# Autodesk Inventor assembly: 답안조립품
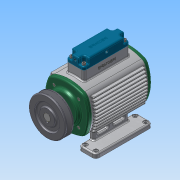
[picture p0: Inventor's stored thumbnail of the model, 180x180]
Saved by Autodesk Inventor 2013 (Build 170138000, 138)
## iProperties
Created: 2015-11
Part Number: 답안조립품
Document SubType Name: Assembly
Designer: Administrator
Mass: 3987.76 g
Surface Area: 3185.16 cm^2
Volume: 1076.11 cm^3
Density: 3.70574 g/cm^3
Author: Administrator
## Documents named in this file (18)
- C:\Users\Administrator\Desktop\351110V1036\답안조립품.iam
- C:\Users\Administrator\Desktop\351110V1036\본체.ipt
- C:\Users\Administrator\Desktop\351110V1036\축.ipt
- C:\Users\Administrator\Desktop\351110V1036\V-벨트풀리.ipt
- C:\Users\Administrator\Desktop\351110V1036\베어링 6203.ipt
- C:\Users\Administrator\Desktop\351110V1036\볼트 M4 x 12.ipt
- C:\Users\Administrator\Desktop\351110V1036\앞커버.ipt
- C:\Users\Administrator\Desktop\351110V1036\오일실 17 30 8.ipt
- C:\Users\Administrator\Desktop\351110V1036\키 - 5 x 5 x 18.ipt
- C:\Users\Administrator\Desktop\351110V1036\멈춤나사 M4x5.ipt
- C:\Users\Administrator\Desktop\351110V1036\뒷커버.ipt
- C:\Users\Administrator\Desktop\351110V1036\부시.ipt
- C:\Users\Administrator\Desktop\351110V1036\스프링1.ipt
- C:\Users\Administrator\Desktop\351110V1036\슬라이드.ipt
- C:\Users\Administrator\Desktop\351110V1036\스프링2.ipt
- C:\Users\Administrator\Desktop\351110V1036\스프링3.ipt
- C:\Users\Administrator\Desktop\351110V1036\볼트 M4 x 16.ipt
- C:\Users\Administrator\Desktop\351110V1036\헤더커버.ipt
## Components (4 placed, 3 different names)
1. 7-베어링 6203:1
2. V-벨트풀리:1 — 플러쉬:1
3. 7-베어링 6203:2
4. 헤더커버:1
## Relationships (1: Flush 1)
- 플러쉬:1 [Flush]: V-벨트풀리:1
